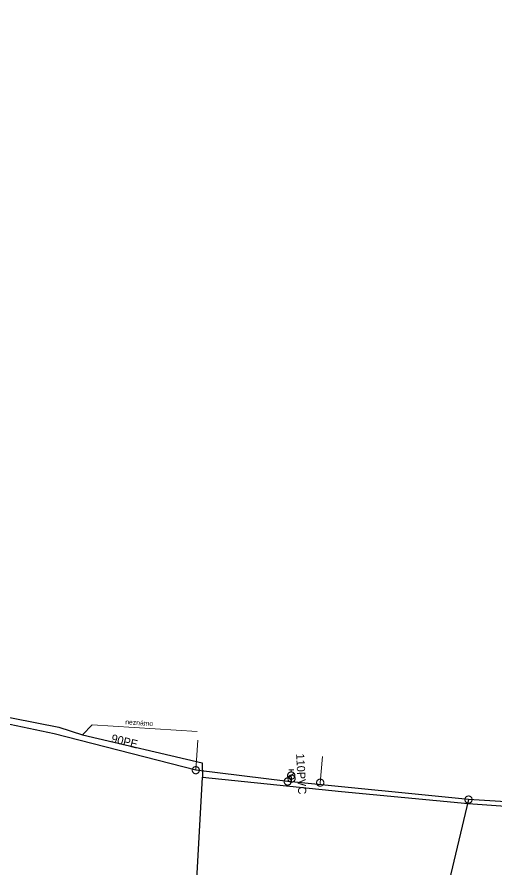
# Model space of a CAD drawing. Extents: x -741806 to -738704, y -1059275 to -1055387.
# Drawn here: x -740655.8 to -740597.4, y -1057576.9 to -1057473.2 of the extents above; entities that cross this region are included whole.
import ezdxf

# ---------------------------------------------------------------- set-up
doc = ezdxf.new("R2010")
doc.units = 0
doc.header["$LTSCALE"] = 0.4
for name, color, linetype, lineweight in [('2', 7, 'Continuous', 25), ('21', 7, 'Continuous', 13), ('50', 7, 'Continuous', 13), ('51', 7, 'Continuous', 13), ('52', 7, 'Continuous', 25), ('56', 7, 'Continuous', 13)]:
    doc.layers.add(name, color=color, linetype=linetype, lineweight=lineweight)
doc.layers.add('53', color=7, linetype='Continuous')
doc.layers.add('55', color=7, linetype='Continuous')

msp = doc.modelspace()

# ---------------------------------------------------------------- linework, layer by layer
at = {"layer": '2'}
for points in [[(-740701.18, -1057473.159), (-740698.129, -1057473.58), (-740689.684, -1057473.824), (-740686.82, -1057473.879), (-740685.879, -1057474.169), (-740685.34, -1057475.12), (-740682.62, -1057479.69), (-740667.039, -1057506.61), (-740665.579, -1057509.429), (-740664.78, -1057511.48), (-740665.629, -1057515.87), (-740666.629, -1057532.149), (-740667.16, -1057536.6), (-740668.18, -1057545.78), (-740668.8, -1057555.2), (-740668.35, -1057556.21), (-740667.51, -1057556.51), (-740662.09, -1057557.53), (-740650.66, -1057559.78), (-740647.78, -1057560.7), (-740633.18, -1057564.139), (-740633.142, -1057565.869)], [(-740702.59, -1057629.575), (-740677.195, -1057630.344), (-740674.756, -1057596.152), (-740674.105, -1057587.855), (-740634.449, -1057589.387), (-740633.142, -1057565.869)], [(-740633.142, -1057565.869), (-740616.157, -1057567.624), (-740600.686, -1057569.098), (-740568.695, -1057571.365), (-740532.184, -1057575.2), (-740517.113, -1057574.642), (-740509.967, -1057572.304)]]:
    msp.add_lwpolyline(points, dxfattribs=at)
at = {"layer": '21'}
msp.add_line((-740633.96, -1057565.02), (-740633.708, -1057561.371), dxfattribs=at)
msp.add_lwpolyline([(-740618.741, -1057566.792), (-740618.769, -1057566.544), (-740618.488, -1057563.334)], dxfattribs=at)
at = {"layer": '50'}
for p, q in [((-740622.615, -1057564.985), (-740622.307, -1057564.985)), ((-740622.307, -1057565.236), (-740622.307, -1057564.985)), ((-740622, -1057564.985), (-740622.307, -1057564.985)), ((-740622.307, -1057565.683), (-740622.624, -1057566)), ((-740622.307, -1057565.683), (-740621.991, -1057565.371))]:
    msp.add_line(p, q, dxfattribs=at)
msp.add_lwpolyline([(-740621.863, -1057565.687), (-740621.865, -1057565.638), (-740621.87, -1057565.592), (-740621.883, -1057565.546), (-740621.9, -1057565.503), (-740621.919, -1057565.463), (-740621.946, -1057565.422), (-740621.975, -1057565.387), (-740622.008, -1057565.352), (-740622.043, -1057565.322), (-740622.083, -1057565.298), (-740622.124, -1057565.276), (-740622.167, -1057565.257), (-740622.213, -1057565.247), (-740622.259, -1057565.239), (-740622.305, -1057565.236), (-740622.351, -1057565.239), (-740622.396, -1057565.244), (-740622.442, -1057565.257), (-740622.486, -1057565.274), (-740622.529, -1057565.295), (-740622.567, -1057565.32), (-740622.604, -1057565.349), (-740622.637, -1057565.382), (-740622.666, -1057565.417), (-740622.693, -1057565.457), (-740622.715, -1057565.498), (-740622.731, -1057565.541), (-740622.745, -1057565.587), (-740622.75, -1057565.633), (-740622.757, -1057565.679), (-740622.754, -1057565.727), (-740622.746, -1057565.773), (-740622.735, -1057565.816), (-740622.719, -1057565.862), (-740622.697, -1057565.903), (-740622.673, -1057565.943), (-740622.643, -1057565.978), (-740622.611, -1057566.013), (-740622.573, -1057566.043), (-740622.535, -1057566.067), (-740622.492, -1057566.089), (-740622.449, -1057566.105), (-740622.406, -1057566.119), (-740622.357, -1057566.127), (-740622.311, -1057566.13), (-740622.265, -1057566.127), (-740622.219, -1057566.119), (-740622.173, -1057566.108), (-740622.13, -1057566.092), (-740622.087, -1057566.07), (-740622.049, -1057566.046), (-740622.011, -1057566.016), (-740621.979, -1057565.984), (-740621.949, -1057565.949), (-740621.925, -1057565.908), (-740621.901, -1057565.868), (-740621.884, -1057565.824), (-740621.874, -1057565.779), (-740621.866, -1057565.733)], close=True, dxfattribs=at)
at = {"layer": '51'}
for points in [[(-740633.522, -1057565.02), (-740633.524, -1057564.975), (-740633.532, -1057564.93), (-740633.544, -1057564.885), (-740633.559, -1057564.843), (-740633.581, -1057564.802), (-740633.605, -1057564.763), (-740633.635, -1057564.728), (-740633.667, -1057564.695), (-740633.703, -1057564.667), (-740633.74, -1057564.642), (-740633.782, -1057564.621), (-740633.825, -1057564.604), (-740633.869, -1057564.592), (-740633.914, -1057564.585), (-740633.96, -1057564.583), (-740634.005, -1057564.585), (-740634.051, -1057564.592), (-740634.095, -1057564.604), (-740634.137, -1057564.621), (-740634.179, -1057564.642), (-740634.217, -1057564.667), (-740634.252, -1057564.695), (-740634.284, -1057564.728), (-740634.314, -1057564.763), (-740634.338, -1057564.802), (-740634.36, -1057564.843), (-740634.375, -1057564.885), (-740634.387, -1057564.93), (-740634.395, -1057564.975), (-740634.397, -1057565.021), (-740634.395, -1057565.066), (-740634.387, -1057565.111), (-740634.375, -1057565.156), (-740634.36, -1057565.198), (-740634.338, -1057565.239), (-740634.314, -1057565.278), (-740634.284, -1057565.313), (-740634.252, -1057565.346), (-740634.217, -1057565.374), (-740634.179, -1057565.399), (-740634.137, -1057565.42), (-740634.095, -1057565.437), (-740634.051, -1057565.448), (-740634.005, -1057565.456), (-740633.96, -1057565.458), (-740633.914, -1057565.456), (-740633.869, -1057565.448), (-740633.825, -1057565.437), (-740633.782, -1057565.42), (-740633.74, -1057565.399), (-740633.703, -1057565.374), (-740633.667, -1057565.346), (-740633.635, -1057565.313), (-740633.605, -1057565.278), (-740633.581, -1057565.239), (-740633.559, -1057565.198), (-740633.544, -1057565.156), (-740633.532, -1057565.111), (-740633.524, -1057565.066), (-740633.522, -1057565.021)], [(-740622.301, -1057566.399), (-740622.303, -1057566.354), (-740622.311, -1057566.309), (-740622.323, -1057566.264), (-740622.338, -1057566.222), (-740622.36, -1057566.181), (-740622.384, -1057566.142), (-740622.414, -1057566.107), (-740622.446, -1057566.074), (-740622.482, -1057566.046), (-740622.519, -1057566.021), (-740622.561, -1057566), (-740622.603, -1057565.983), (-740622.647, -1057565.971), (-740622.693, -1057565.964), (-740622.739, -1057565.962), (-740622.784, -1057565.964), (-740622.83, -1057565.971), (-740622.874, -1057565.983), (-740622.916, -1057566), (-740622.958, -1057566.021), (-740622.995, -1057566.046), (-740623.031, -1057566.074), (-740623.063, -1057566.107), (-740623.093, -1057566.142), (-740623.117, -1057566.181), (-740623.139, -1057566.222), (-740623.154, -1057566.264), (-740623.166, -1057566.309), (-740623.174, -1057566.354), (-740623.176, -1057566.4), (-740623.174, -1057566.445), (-740623.166, -1057566.49), (-740623.154, -1057566.535), (-740623.139, -1057566.577), (-740623.117, -1057566.618), (-740623.093, -1057566.657), (-740623.063, -1057566.692), (-740623.031, -1057566.725), (-740622.995, -1057566.753), (-740622.958, -1057566.778), (-740622.916, -1057566.799), (-740622.874, -1057566.816), (-740622.83, -1057566.827), (-740622.784, -1057566.835), (-740622.739, -1057566.837), (-740622.693, -1057566.835), (-740622.647, -1057566.827), (-740622.603, -1057566.816), (-740622.561, -1057566.799), (-740622.519, -1057566.778), (-740622.482, -1057566.753), (-740622.446, -1057566.725), (-740622.414, -1057566.692), (-740622.384, -1057566.657), (-740622.36, -1057566.618), (-740622.338, -1057566.577), (-740622.323, -1057566.535), (-740622.311, -1057566.49), (-740622.303, -1057566.445), (-740622.301, -1057566.4)], [(-740621.831, -1057566.047), (-740621.833, -1057566.002), (-740621.841, -1057565.957), (-740621.853, -1057565.912), (-740621.869, -1057565.87), (-740621.89, -1057565.829), (-740621.914, -1057565.79), (-740621.944, -1057565.755), (-740621.976, -1057565.722), (-740622.012, -1057565.694), (-740622.049, -1057565.669), (-740622.091, -1057565.648), (-740622.134, -1057565.631), (-740622.178, -1057565.619), (-740622.223, -1057565.612), (-740622.269, -1057565.61), (-740622.315, -1057565.612), (-740622.36, -1057565.619), (-740622.404, -1057565.631), (-740622.446, -1057565.648), (-740622.488, -1057565.669), (-740622.526, -1057565.694), (-740622.561, -1057565.722), (-740622.593, -1057565.755), (-740622.623, -1057565.79), (-740622.647, -1057565.829), (-740622.669, -1057565.87), (-740622.684, -1057565.912), (-740622.696, -1057565.957), (-740622.704, -1057566.002), (-740622.706, -1057566.048), (-740622.704, -1057566.093), (-740622.696, -1057566.138), (-740622.684, -1057566.183), (-740622.669, -1057566.225), (-740622.647, -1057566.266), (-740622.623, -1057566.305), (-740622.593, -1057566.34), (-740622.561, -1057566.373), (-740622.526, -1057566.401), (-740622.488, -1057566.426), (-740622.446, -1057566.447), (-740622.404, -1057566.464), (-740622.36, -1057566.475), (-740622.315, -1057566.483), (-740622.269, -1057566.485), (-740622.223, -1057566.483), (-740622.178, -1057566.475), (-740622.134, -1057566.464), (-740622.091, -1057566.447), (-740622.049, -1057566.426), (-740622.012, -1057566.401), (-740621.976, -1057566.373), (-740621.944, -1057566.34), (-740621.914, -1057566.305), (-740621.89, -1057566.266), (-740621.869, -1057566.225), (-740621.853, -1057566.183), (-740621.841, -1057566.138), (-740621.833, -1057566.093), (-740621.831, -1057566.048)], [(-740618.816, -1057566.109), (-740618.86, -1057566.116), (-740618.904, -1057566.128), (-740618.948, -1057566.145), (-740618.988, -1057566.165), (-740619.026, -1057566.19), (-740619.062, -1057566.22), (-740619.094, -1057566.252), (-740619.123, -1057566.288), (-740619.147, -1057566.326), (-740619.168, -1057566.367), (-740619.184, -1057566.41), (-740619.196, -1057566.455), (-740619.203, -1057566.5), (-740619.205, -1057566.545), (-740619.202, -1057566.591), (-740619.195, -1057566.637), (-740619.184, -1057566.681), (-740619.167, -1057566.723), (-740619.145, -1057566.764), (-740619.12, -1057566.802), (-740619.091, -1057566.837), (-740619.059, -1057566.87), (-740619.023, -1057566.898), (-740618.985, -1057566.923), (-740618.943, -1057566.944), (-740618.9, -1057566.96), (-740618.857, -1057566.972), (-740618.811, -1057566.979), (-740618.765, -1057566.981), (-740618.719, -1057566.979), (-740618.675, -1057566.971), (-740618.631, -1057566.959), (-740618.587, -1057566.942), (-740618.547, -1057566.922), (-740618.509, -1057566.896), (-740618.473, -1057566.867), (-740618.441, -1057566.835), (-740618.412, -1057566.799), (-740618.388, -1057566.76), (-740618.367, -1057566.72), (-740618.351, -1057566.677), (-740618.339, -1057566.632), (-740618.333, -1057566.587), (-740618.33, -1057566.542), (-740618.333, -1057566.496), (-740618.34, -1057566.45), (-740618.352, -1057566.406), (-740618.368, -1057566.364), (-740618.39, -1057566.323), (-740618.415, -1057566.284), (-740618.444, -1057566.249), (-740618.476, -1057566.217), (-740618.512, -1057566.188), (-740618.55, -1057566.163), (-740618.592, -1057566.143), (-740618.635, -1057566.126), (-740618.678, -1057566.115), (-740618.724, -1057566.108), (-740618.77, -1057566.106), (-740618.815, -1057566.109)], [(-740601.094, -1057568.579), (-740601.094, -1057568.624), (-740601.09, -1057568.67), (-740601.081, -1057568.715), (-740601.067, -1057568.758), (-740601.049, -1057568.801), (-740601.026, -1057568.841), (-740601, -1057568.878), (-740600.97, -1057568.913), (-740600.935, -1057568.943), (-740600.899, -1057568.97), (-740600.859, -1057568.993), (-740600.818, -1057569.013), (-740600.774, -1057569.028), (-740600.73, -1057569.037), (-740600.684, -1057569.042), (-740600.638, -1057569.043), (-740600.593, -1057569.039), (-740600.548, -1057569.029), (-740600.504, -1057569.015), (-740600.462, -1057568.997), (-740600.422, -1057568.974), (-740600.385, -1057568.948), (-740600.351, -1057568.917), (-740600.32, -1057568.884), (-740600.292, -1057568.847), (-740600.269, -1057568.807), (-740600.25, -1057568.766), (-740600.236, -1057568.722), (-740600.226, -1057568.677), (-740600.22, -1057568.632), (-740600.22, -1057568.587), (-740600.225, -1057568.541), (-740600.234, -1057568.496), (-740600.247, -1057568.453), (-740600.266, -1057568.41), (-740600.288, -1057568.37), (-740600.315, -1057568.333), (-740600.345, -1057568.298), (-740600.379, -1057568.268), (-740600.416, -1057568.241), (-740600.455, -1057568.218), (-740600.497, -1057568.198), (-740600.541, -1057568.184), (-740600.585, -1057568.174), (-740600.631, -1057568.169), (-740600.677, -1057568.168), (-740600.722, -1057568.173), (-740600.767, -1057568.182), (-740600.811, -1057568.196), (-740600.853, -1057568.214), (-740600.892, -1057568.237), (-740600.93, -1057568.263), (-740600.964, -1057568.294), (-740600.995, -1057568.327), (-740601.022, -1057568.364), (-740601.046, -1057568.404), (-740601.064, -1057568.445), (-740601.079, -1057568.489), (-740601.089, -1057568.534), (-740601.094, -1057568.578)]]:
    msp.add_lwpolyline(points, dxfattribs=at)
at = {"layer": '52'}
msp.add_line((-740600.658, -1057568.607), (-740606.199, -1057591.97), dxfattribs=at)
for points in [[(-740622.261, -1057566.439), (-740622.739, -1057566.399), (-740633.96, -1057565.02), (-740651.25, -1057560.57), (-740662.129, -1057558.3), (-740670.91, -1057556.8), (-740669.903, -1057546.362)], [(-740622.261, -1057566.439), (-740622.269, -1057566.047), (-740622.307, -1057565.679)], [(-740551.934, -1057571.904), (-740584.473, -1057569.593), (-740600.658, -1057568.607), (-740622.261, -1057566.439)]]:
    msp.add_lwpolyline(points, dxfattribs=at)
at = {"layer": '56'}
msp.add_lwpolyline([(-740633.789, -1057560.29), (-740646.629, -1057559.5), (-740647.78, -1057560.7)], dxfattribs=at)

# ---------------------------------------------------------------- texts
at = {"layer": '53'}
for s, rotation, p in [('90PE', 346, (-740644.358, -1057561.583)), ('110PVC', 273, (-740621.711, -1057563.019))]:
    msp.add_text(s, height=1, rotation=rotation, dxfattribs=at).set_placement(p)
at = {"layer": '55'}
msp.add_text('neznámo ', height=0.6, rotation=356, dxfattribs=at).set_placement((-740642.584, -1057559.417))

doc.saveas('drawing.dxf')
